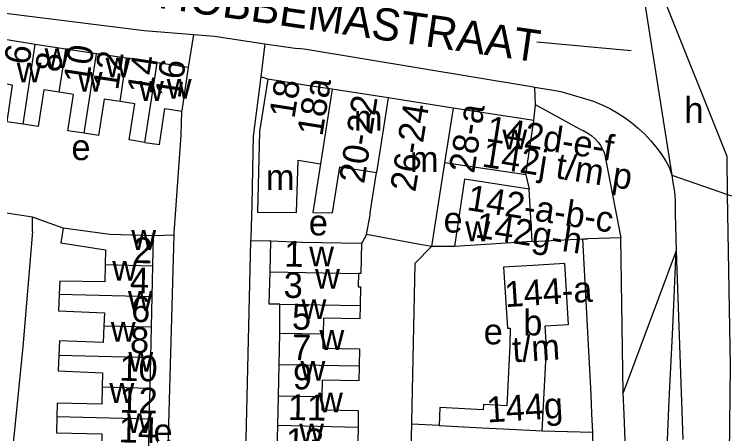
# Model space of a CAD drawing. Extents: x 161775 to 163181, y 382878 to 383925.
# Drawn here: x 163069.3 to 163181, y 383216 to 383281.3 of the extents above; entities that cross this region are included whole.
import ezdxf

# ---------------------------------------------------------------- set-up
doc = ezdxf.new("R2010")
doc.units = 0
for name, color, linetype in [('BLT_Basislijn', 7, 'Continuous'), ('BLT_Bebouwing', 7, 'Continuous'), ('BLT_Centroide', 7, 'Continuous'), ('BLT_Huisnummer', 7, 'Continuous'), ('BLT_Huisnummer_ tussenligend', 7, 'Continuous'), ('BLT_Huisnummer_reeks', 7, 'Continuous'), ('BLT_Onderverdeling_panden', 7, 'Continuous'), ('BLT_Straatnaam', 7, 'Continuous'), ('BLT_Vlakafsluiter', 7, 'Continuous')]:
    doc.layers.add(name, color=color, linetype=linetype)

msp = doc.modelspace()

# ---------------------------------------------------------------- linework, layer by layer
at = {"layer": 'BLT_Basislijn'}
for p, q in [((163060.03, 383282.43), (163089.53, 383278.73)), ((163089.53, 383278.73), (163097.26, 383278.11)), ((163096.4, 383273.01), (163097.26, 383278.11)), ((163108.31, 383276.7), (163113.39, 383275.94)), ((163150.66, 383277.01), (163165.35, 383275.62)), ((163108.77, 383271.16), (163107.66, 383271.53)), ((163150.32, 383269.9), (163149.84, 383269.99)), ((163150.46, 383267.18), (163150.32, 383269.9)), ((163150.19, 383264.74), (163150.46, 383267.18)), ((163157.34, 383263.4), (163150.46, 383267.18)), ((163161.19, 383259.63), (163163.76, 383246.49)), ((163171.27, 383257.48), (163171.67, 383256.23)), ((163148.93, 383256.28), (163149.48, 383254.08)), ((163171.67, 383256.23), (163171.85, 383255.09)), ((163072.13, 383249.73), (163061.97, 383251.19)), ((163076.88, 383248.01), (163072.13, 383249.73)), ((163172.18, 383250.16), (163172.37, 383244.48)), ((163094.19, 383246.92), (163090.95, 383246.83)), ((163149.92, 383245.91), (163157.81, 383246.32)), ((163157.81, 383246.32), (163158.57, 383246.36)), ((163159.1, 383222.09), (163157.81, 383246.32)), ((163163.76, 383246.49), (163158.57, 383246.36)), ((163164.09, 383222.35), (163163.76, 383246.49)), ((163109.24, 383246.02), (163106.09, 383245.95)), ((163137.85, 383245.12), (163134.24, 383245.12)), ((163172.37, 383244.48), (163164.09, 383222.35)), ((163172.37, 383244.48), (163173.41, 383215.12)), ((163135.42, 383217.3), (163131.12, 383217.49)), ((163151.49, 383216.45), (163159.35, 383216.26))]:
    msp.add_line(p, q, dxfattribs=at)
for points in [[(163108.31, 383276.7), (163107.66, 383271.53)], [(163149.84, 383269.99), (163114.4, 383275.84), (163113.39, 383275.94)], [(163107.66, 383271.53), (163106.5, 383262.32), (163106.38, 383257.24), (163106.28, 383251.58), (163106.1, 383246.43), (163106.09, 383245.95)], [(163159.71, 383267.64), (163154.42, 383269.21), (163150.32, 383269.9)], [(163159.71, 383267.64), (163160.93, 383267.13), (163162.12, 383266.55), (163163.28, 383265.89), (163164.4, 383265.17), (163165.46, 383264.38), (163166.48, 383263.53), (163167.45, 383262.62), (163168.36, 383261.65), (163169.21, 383260.63), (163170, 383259.56), (163170.72, 383258.44), (163171.27, 383257.48)], [(163094.19, 383246.92), (163094.2, 383247.28), (163095.27, 383262.46), (163095.39, 383266.22)], [(163157.34, 383263.4), (163158, 383263.13), (163158.62, 383262.79), (163159.2, 383262.39), (163159.73, 383261.92), (163160.2, 383261.39), (163160.61, 383260.82), (163160.95, 383260.2), (163161.19, 383259.63)], [(163180.37, 383253.26), (163180.27, 383259.17)], [(163171.85, 383255.09), (163172.07, 383253.64), (163172.18, 383252.33), (163172.21, 383251.02), (163172.18, 383250.16)], [(163180.54, 383203.71), (163180.82, 383226.6), (163180.37, 383253.26)], [(163072.11, 383247.48), (163072.13, 383247.79), (163072.13, 383249.73)], [(163072.11, 383247.48), (163070.59, 383229.54), (163066.38, 383187.7), (163066.24, 383186.34)], [(163092.4, 383184.45), (163092.46, 383186.32), (163094.19, 383246.92)], [(163124.13, 383246.99), (163123.51, 383245.86), (163123.35, 383245.65)], [(163106.09, 383245.95), (163104.73, 383188.79), (163104.46, 383184.66), (163104.29, 383181.92)], [(163134.24, 383245.12), (163131.67, 383242.48), (163131.13, 383217.83), (163131.12, 383217.49)], [(163170.93, 383213.84), (163171.28, 383221.24), (163171.85, 383232.5), (163172.37, 383244.48)], [(163159.35, 383216.26), (163159.24, 383219.1), (163159.1, 383222.09)], [(163163.96, 383180.39), (163164.24, 383185.91), (163164.44, 383191.43), (163164.56, 383196.96), (163164.6, 383202.49), (163164.57, 383208.02), (163164.45, 383213.54), (163164.25, 383219.07), (163164.09, 383222.35)], [(163131.12, 383217.49), (163130.29, 383187.3), (163129.95, 383182.62), (163129.81, 383180.67)], [(163158.96, 383180.68), (163159.24, 383186.16), (163159.45, 383191.65), (163159.56, 383197.14), (163159.6, 383202.63), (163159.56, 383208.12), (163159.44, 383213.61), (163159.35, 383216.26)]]:
    msp.add_lwpolyline(points, dxfattribs=at)
at = {"layer": 'BLT_Bebouwing'}
for p, q in [((163072.55, 383276.6), (163067.79, 383277.33)), ((163077.31, 383275.87), (163072.55, 383276.6)), ((163082.07, 383275.15), (163077.31, 383275.87)), ((163086.78, 383274.45), (163082.07, 383275.15)), ((163091.51, 383273.74), (163086.78, 383274.45)), ((163096.4, 383273.01), (163091.51, 383273.74)), ((163118.77, 383269.61), (163114.84, 383270.22)), ((163127.49, 383268.26), (163118.77, 383269.61)), ((163137.63, 383266.69), (163127.49, 383268.26)), ((163150.19, 383264.74), (163137.63, 383266.69)), ((163148.93, 383256.28), (163150.19, 383264.74)), ((163136.29, 383258.17), (163134.24, 383245.12)), ((163148.93, 383256.28), (163136.29, 383258.17)), ((163149.92, 383245.91), (163149.48, 383254.08)), ((163090.85, 383242.15), (163090.95, 383246.83)), ((163131.85, 383245.57), (163124.13, 383246.99)), ((163109.12, 383241.21), (163109.24, 383246.02)), ((163134.24, 383245.12), (163131.85, 383245.57)), ((163149.92, 383245.91), (163137.85, 383245.12)), ((163090.74, 383237.39), (163090.85, 383242.15)), ((163090.63, 383232.63), (163090.74, 383237.39)), ((163110.64, 383231.61), (163110.61, 383236.17)), ((163090.53, 383227.87), (163090.63, 383232.63)), ((163110.53, 383226.75), (163110.64, 383231.61)), ((163090.42, 383223.11), (163090.53, 383227.87)), ((163110.41, 383221.88), (163110.53, 383226.75)), ((163090.31, 383218.35), (163090.42, 383223.11)), ((163110.3, 383217.27), (163110.41, 383221.88)), ((163090.21, 383213.59), (163090.31, 383218.35)), ((163110.19, 383212.53), (163110.3, 383217.27))]:
    msp.add_line(p, q, dxfattribs=at)
for points in [[(163095.39, 383266.22), (163095.4, 383266.29), (163096.4, 383273.01)], [(163108.77, 383271.16), (163107.49, 383263.04)], [(163114.84, 383270.22), (163108.77, 383271.16)], [(163070.68, 383264.16), (163068.15, 383264.53), (163069.02, 383270.24), (163066.76, 383270.59)], [(163076.29, 383269.14), (163073.87, 383269.5), (163073, 383263.82), (163070.68, 383264.16)], [(163080.15, 383262.76), (163077.62, 383263.14), (163078.49, 383268.8), (163076.29, 383269.14)], [(163085.75, 383267.69), (163083.26, 383268.07), (163082.4, 383262.43), (163080.15, 383262.76)], [(163089.62, 383261.35), (163087.17, 383261.73), (163088.03, 383267.34), (163085.75, 383267.69)], [(163089.62, 383261.35), (163091.88, 383261.01), (163092.73, 383266.62), (163095.39, 383266.22)], [(163107.49, 383263.04), (163107.15, 383250.5), (163113.25, 383250.44), (163113.47, 383258.56), (163116.95, 383258.02)], [(163116.95, 383258.02), (163115.78, 383250.42), (163118.83, 383250.39), (163119.8, 383256.55)], [(163119.8, 383256.55), (163119.96, 383257.56), (163125.67, 383256.66)], [(163124.13, 383246.99), (163124.68, 383250), (163124.68, 383250.36), (163125.67, 383256.66)], [(163149.48, 383254.08), (163139.38, 383255.62), (163137.85, 383245.12)], [(163076.88, 383248.01), (163076.51, 383245.71), (163083.47, 383244.6), (163083.43, 383242.33)], [(163090.95, 383246.83), (163084.14, 383246.99), (163076.88, 383248.01)], [(163109.24, 383246.02), (163114.06, 383245.81), (163123.35, 383245.65)], [(163123.35, 383245.65), (163123.26, 383240.95), (163122.88, 383240.95)], [(163083.43, 383242.33), (163083.39, 383239.64), (163076.37, 383239.76), (163076.29, 383237.74)], [(163151.49, 383216.45), (163152.22, 383230.25), (163152.09, 383230.26), (163151.93, 383232.78), (163155.6, 383233.01), (163155, 383242.52), (163150.01, 383242.21), (163145.48, 383241.92), (163146.08, 383232.42), (163146.52, 383232.45), (163146.47, 383229.78)], [(163110.61, 383236.17), (163108.99, 383236.17), (163109.12, 383241.21)], [(163122.88, 383240.95), (163122.84, 383238.87), (163123.2, 383238.86), (163123.15, 383235.95)], [(163076.29, 383237.74), (163076.18, 383235.13), (163083.31, 383234.82), (163083.23, 383232.81)], [(163123.15, 383235.95), (163123.11, 383233.89), (163117.42, 383233.99), (163117.37, 383231.49)], [(163083.23, 383232.81), (163083.11, 383230.19), (163076.3, 383230.48), (163076.2, 383228.22)], [(163117.37, 383231.49), (163117.33, 383229.3), (163123.03, 383229.2), (163122.98, 383226.52)], [(163146.47, 383229.78), (163145.97, 383220.36), (163142.34, 383220.56), (163142.3, 383219.74), (163135.57, 383220.1), (163135.42, 383217.3)], [(163076.2, 383228.22), (163076.1, 383225.8), (163083.01, 383225.51), (163082.96, 383223.29)], [(163122.98, 383226.52), (163122.94, 383224.26), (163117.24, 383224.37), (163117.19, 383221.76)], [(163082.96, 383223.29), (163082.9, 383220.63), (163075.97, 383220.79), (163075.92, 383218.7)], [(163117.19, 383221.76), (163117.15, 383219.72), (163122.85, 383219.61), (163122.81, 383216.98)], [(163075.92, 383218.7), (163075.86, 383216.13), (163082.9, 383215.97), (163082.85, 383213.77)], [(163135.42, 383217.3), (163142.14, 383216.92), (163146.49, 383216.72), (163151.49, 383216.45)], [(163122.81, 383216.98), (163122.77, 383214.85), (163122.72, 383212.24), (163119.95, 383212.3)]]:
    msp.add_lwpolyline(points, dxfattribs=at)
at = {"layer": 'BLT_Onderverdeling_panden'}
for p, q in [((163070.68, 383264.16), (163072.55, 383276.6)), ((163076.29, 383269.14), (163077.31, 383275.87)), ((163080.15, 383262.76), (163082.07, 383275.15)), ((163085.75, 383267.69), (163086.78, 383274.45)), ((163089.62, 383261.35), (163091.51, 383273.74)), ((163118.77, 383269.61), (163116.95, 383258.02)), ((163127.49, 383268.26), (163125.67, 383256.66)), ((163137.63, 383266.69), (163136.29, 383258.17)), ((163083.43, 383242.33), (163090.85, 383242.15)), ((163109.12, 383241.21), (163122.88, 383240.95)), ((163076.29, 383237.74), (163090.74, 383237.39)), ((163083.23, 383232.81), (163090.63, 383232.63)), ((163076.2, 383228.22), (163090.53, 383227.87)), ((163082.96, 383223.29), (163090.42, 383223.11)), ((163075.92, 383218.7), (163090.31, 383218.35)), ((163122.81, 383216.98), (163110.3, 383217.27))]:
    msp.add_line(p, q, dxfattribs=at)
for points in [[(163110.61, 383236.17), (163123.15, 383235.95)], [(163117.37, 383231.49), (163110.64, 383231.61)], [(163122.98, 383226.52), (163110.53, 383226.75)], [(163117.19, 383221.76), (163110.41, 383221.88)]]:
    msp.add_lwpolyline(points, dxfattribs=at)
at = {"layer": 'BLT_Vlakafsluiter'}
for p, q in [((163180.27, 383259.17), (163165.3, 383296.62)), ((163165.3, 383296.62), (163171.67, 383256.23)), ((163171.67, 383256.23), (163180.37, 383253.26)), ((163180.37, 383253.26), (163180.99, 383253.05))]:
    msp.add_line(p, q, dxfattribs=at)
msp.add_lwpolyline([(163097.26, 383278.11), (163100.48, 383277.86), (163108.31, 383276.7)], dxfattribs=at)

# ---------------------------------------------------------------- texts
at = {"layer": 'BLT_Centroide'}
for s, p in [('w', (163074, 383272.92)), ('w', (163083.5, 383271.48)), ('w', (163069.66, 383270.67)), ('w', (163079.17, 383269.25)), ('w', (163088.7, 383267.81)), ('w', (163093.03, 383268.14)), ('h', (163173.64, 383264.38)), ('m', (163122.17, 383263.16)), ('w', (163145.29, 383260.27)), ('e', (163078.18, 383258.59)), ('m', (163130.88, 383256.75)), ('m', (163108.46, 383253.93)), ('e', (163115.14, 383246.87)), ('e', (163136.13, 383247.31)), ('w', (163139.51, 383245.97)), ('w', (163087.5, 383244.62)), ('w', (163115.2, 383242.06)), ('w', (163084.54, 383239.84)), ('w', (163116.12, 383238.56)), ('w', (163086.98, 383235.16)), ('w', (163114.02, 383233.84)), ('b', (163148.54, 383231.31)), ('w', (163084.31, 383230.34)), ('e', (163142.38, 383229.92)), ('w', (163116.8, 383229.06)), ('w', (163087.05, 383225.66)), ('w', (163113.85, 383224.25)), ('w', (163084.1, 383220.81)), ('w', (163116.59, 383219.34)), ('w', (163086.84, 383216.12)), ('e', (163090.95, 383214.37)), ('w', (163113.65, 383214.53))]:
    msp.add_text(s, height=4, dxfattribs=at).set_placement(p)
at = {"layer": 'BLT_Huisnummer'}
for s, rotation, p in [('6', 81.3254, (163071.61, 383273.29)), ('10', 81.3254, (163080.85, 383270.31)), ('16', 81.3254, (163095.13, 383268.05)), ('18', 81.0739, (163112.9, 383264.95)), ('18a', 81.0739, (163117.25, 383262.19)), ('2', 358.648, (163087.75, 383242.59)), ('1', 358.9574, (163111.3, 383242.02)), ('6', 358.6476, (163087.44, 383233.41)), ('5', 358.9616, (163112.5, 383232.24)), ('10', 358.647, (163085.61, 383224.27)), ('9', 358.9616, (163112.64, 383222.94)), ('14', 358.6468, (163085.51, 383214.67)), ('13', 358.9616, (163111.52, 383212.9))]:
    msp.add_text(s, height=4, rotation=rotation, dxfattribs=at).set_placement(p)
at = {"layer": 'BLT_Huisnummer_ tussenligend'}
for s, rotation, p in [('8', 81.3254, (163076.44, 383272.11)), ('12', 81.3254, (163085.44, 383269.36)), ('14', 81.3254, (163090.76, 383268.7)), ('4', 358.648, (163087.26, 383237.92)), ('3', 358.9574, (163111.2, 383237.17)), ('8', 358.6476, (163087.27, 383228.61)), ('7', 358.9616, (163112.5, 383227.48)), ('12', 358.647, (163085.62, 383219.29)), ('11', 358.9616, (163111.86, 383218.16))]:
    msp.add_text(s, height=4, rotation=rotation, dxfattribs=at).set_placement(p)
at = {"layer": 'BLT_Huisnummer_reeks'}
for s, rotation, p in [('20-22', 81.0719, (163123.76, 383254.8)), ('26-24', 81.0693, (163131.73, 383253.51)), ('28-a', 81.0709, (163140.88, 383256.41)), ('142d-e-f', 351.0721, (163142.61, 383261.55)), ('142j t/m p', 351.0721, (163141.97, 383257.6)), ('142-a-b-c', 351.0721, (163139.62, 383250.84)), ('142g-h', 351.0721, (163140.92, 383246.59)), ('144-a', 3.6181, (163145.75, 383235.7)), ('t/m', 3.6181, (163146.94, 383227.12)), ('144g', 3.6181, (163142.96, 383217.75))]:
    msp.add_text(s, height=4, rotation=rotation, dxfattribs=at).set_placement(p)
at = {"layer": 'BLT_Straatnaam'}
msp.add_text('HOBBEMASTRAAT', height=5, rotation=351.8032, dxfattribs=at).set_placement((163091.58, 383282.31))

doc.saveas('drawing.dxf')
